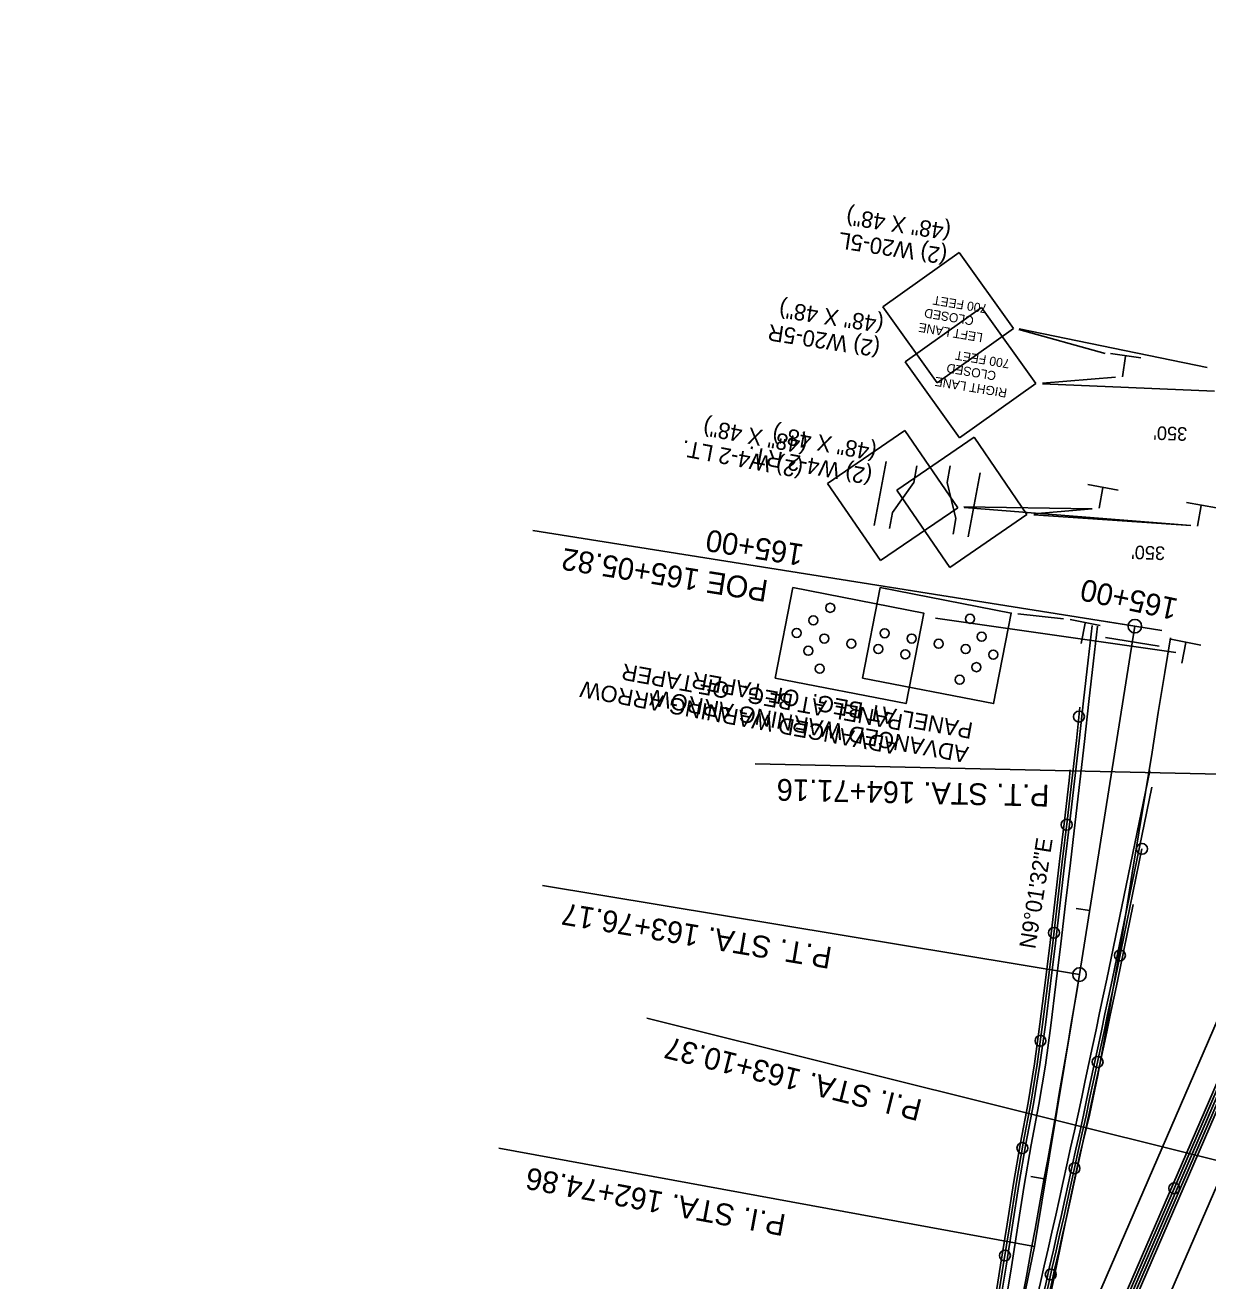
# Model space of a CAD drawing. Extents: x 659657 to 668193, y 633084 to 648639.
# Drawn here: x 661111.9 to 661546.4, y 641402.5 to 641864.1 of the extents above; entities that cross this region are included whole.
import ezdxf

# ---------------------------------------------------------------- set-up
doc = ezdxf.new("R2010")
doc.units = 0
for name, color, linetype in [('R_Border Prem', 7, 'Continuous'), ('R_Draft', 7, 'Continuous'), ('R_MOT_Stage 1_Striping', 7, 'Continuous'), ('R_MOT_Stage 1C_Striping', 7, 'Continuous'), ('R_MOT_Stage 2', 7, 'Continuous'), ('R_MOT_Stage 2_Striping', 7, 'Continuous'), ('R_MOT_Stage 3', 7, 'Continuous'), ('R_MOT_Stage 3_Striping', 7, 'Continuous'), ('R_MOT_Stage 4', 7, 'Continuous'), ('R_MOT_Stage 4_Striping', 7, 'Continuous'), ('R_MOT_Stage 4_Striping_PPM', 7, 'Continuous'), ('R_MOT_Stage 5_Striping_PPM', 7, 'Continuous'), ('S_EXISTING_ALIGNMENT', 7, 'Continuous'), ('T_Notes', 7, 'Continuous'), ('T_SIGNAL CONTROL CABINET', 7, 'Continuous')]:
    doc.layers.add(name, color=color, linetype=linetype)

msp = doc.modelspace()

# ---------------------------------------------------------------- linework, layer by layer
at = {"layer": 'R_Border Prem'}
msp.add_arc((665219.85, 639999.01), 3863.72, 156.12343, 201.98495, dxfattribs=at)
at = {"layer": 'R_Draft'}
for p, q in [((661435.19, 641740.31), (661463.19, 641760.29)), ((661463.19, 641760.29), (661483.17, 641732.29)), ((661435.19, 641740.31), (661455.17, 641712.33)), ((661510.59, 641743.37), (661521.72, 641741.76)), ((661516.1, 641742.41), (661515.01, 641734.81)), ((661512.51, 641734.61), (661485.66, 641732.49)), ((661455.17, 641712.33), (661483.17, 641732.29)), ((661548.84, 641729.52), (661485.67, 641732.19)), ((661460.5, 641712.56), (661432.13, 641693.12)), ((661479.94, 641684.18), (661460.5, 641712.56)), ((661451.7, 641702.05), (661450.56, 641695.96)), ((661462.75, 641699.46), (661458.36, 641675.94)), ((661451.57, 641664.75), (661432.13, 641693.12)), ((661450.56, 641695.96), (661453.86, 641682.77)), ((661502.35, 641695.26), (661513.41, 641693.19)), ((661507.83, 641694.07), (661506.42, 641686.52)), ((661538.51, 641688.64), (661549.58, 641686.63)), ((661479.94, 641684.18), (661451.57, 641664.75)), ((661503.93, 641686.3), (661482.41, 641684.4)), ((661540.13, 641680.09), (661482.42, 641684.01)), ((661543.99, 641687.48), (661542.62, 641679.92)), ((661453.86, 641682.77), (661452.78, 641676.98)), ((661493.35, 641645.81), (661476.62, 641647.68)), ((661495.84, 641645.54), (661506.88, 641643.38)), ((661501.3, 641644.3), (661499.83, 641636.77))]:
    msp.add_line(p, q, dxfattribs=at)
msp.add_lwpolyline([(661419.56, 641624.08), (661467.64, 641614.69), (661474.14, 641647.96), (661426.05, 641657.35)], close=True, dxfattribs=at)
for centre in [(661459.02, 641645.85), (661427.65, 641640.55), (661437.57, 641638.61), (661447.49, 641636.68), (661463.28, 641639.27), (661457.41, 641634.74), (661467.54, 641632.68), (661461.37, 641628.08), (661455.21, 641623.47)]:
    msp.add_circle(centre, 1.66, dxfattribs=at)
at = {"layer": 'R_MOT_Stage 1_Striping'}
for points in [[(661655.56, 641586.4), (661380.13, 641592.5)], [(661621.93, 641428.73), (661340.26, 641499.07)]]:
    msp.add_lwpolyline(points, dxfattribs=at)
at = {"layer": 'R_MOT_Stage 1C_Striping'}
for radius in [3799.97, 3788.97]:
    msp.add_arc((665219.85, 639999.01), radius, 157.70222, 174.95222, dxfattribs=at)
at = {"layer": 'R_MOT_Stage 2'}
for points in [[(661469.87, 641393.19), (661472.24, 641407.94), (661474.6, 641423), (661476.98, 641437.91), (661479.55, 641452.92), (661482.35, 641467.62), (661484.72, 641482.04), (661486.69, 641496.6), (661488.56, 641511.83), (661490.43, 641526.67), (661492.15, 641541.5), (661493.88, 641556.43), (661495.67, 641571.33), (661497.39, 641586.18), (661499.08, 641601.03), (661500.66, 641615.73), (661502.43, 641630.69), (661503.91, 641643.44)], [(661452.51, 641298.04), (661453.61, 641304.72), (661455.98, 641319.49), (661458.36, 641334.3), (661460.77, 641349.1), (661463.14, 641363.86), (661465.47, 641378.69), (661467.9, 641393.51), (661470.27, 641408.25), (661472.62, 641423.31), (661475.01, 641438.24), (661477.58, 641453.27), (661480.38, 641467.97), (661482.74, 641482.33), (661484.71, 641496.85), (661486.58, 641512.08), (661488.44, 641526.91), (661490.16, 641541.73), (661491.89, 641556.67), (661493.69, 641571.56), (661495.4, 641586.41), (661495.85, 641590.4)]]:
    msp.add_lwpolyline(points, dxfattribs=at)
for centre in [(661499.03, 641609.91), (661494.52, 641570.17), (661489.86, 641530.44), (661484.89, 641490.75), (661478.26, 641451.31), (661471.84, 641411.83)]:
    msp.add_circle(centre, 2, dxfattribs=at)
at = {"layer": 'R_MOT_Stage 2_Striping'}
for p, q in [((661499.23, 641515.1), (661519.57, 641643.15)), ((661482.65, 641415.14), (661499.23, 641515.1)), ((661462.54, 641315.82), (661482.65, 641415.14))]:
    msp.add_line(p, q, dxfattribs=at)
for points in [[(661519.57, 641643.15), (661298.44, 641678.27)], [(661471.85, 641392.87), (661474.22, 641407.63), (661476.57, 641422.69), (661478.96, 641437.59), (661481.52, 641452.56), (661484.32, 641467.28), (661486.7, 641481.74), (661488.67, 641496.34), (661490.55, 641511.58), (661492.41, 641526.43), (661494.14, 641541.27), (661495.87, 641556.2), (661497.66, 641571.09), (661499.37, 641585.95), (661501.07, 641600.81), (661502.65, 641615.51), (661504.42, 641630.46), (661505.89, 641643.12)], [(661509.69, 641644.72), (661529.44, 641641.58)], [(661487.01, 641389.87), (661490.06, 641404.53), (661493.11, 641419.47), (661496.16, 641434.17), (661499.38, 641448.85), (661502.86, 641463.46), (661505.96, 641478.08), (661508.65, 641492.8), (661511.23, 641507.99), (661513.78, 641522.77), (661516.2, 641537.57), (661518.61, 641552.38), (661521.08, 641567.18), (661523.49, 641581.98), (661525.87, 641596.78), (661528.12, 641611.37), (661530.57, 641626.18), (661532.63, 641638.82)], [(661508.78, 641638.97), (661528.53, 641635.83)], [(661655.56, 641586.4), (661380.13, 641592.5)], [(661499.23, 641515.1), (661301.92, 641547.83)], [(661498.03, 641539.42), (661502.97, 641538.64)], [(661621.93, 641428.73), (661340.26, 641499.07)], [(661482.65, 641415.14), (661285.95, 641451.34)], [(661481.35, 641440.93), (661486.27, 641440.04)]]:
    msp.add_lwpolyline(points, dxfattribs=at)
for centre in [(661519.57, 641643.15), (661499.23, 641515.1)]:
    msp.add_circle(centre, 2.5, dxfattribs=at)
msp.add_arc((655846.87, 642452.58), 5729.58, 348.556437, 350.582878, dxfattribs=at)
at = {"layer": 'R_MOT_Stage 3'}
msp.add_line((661511.19, 641513.05), (661525.86, 641583.97), dxfattribs=at)
for centre in [(661522.19, 641561.29), (661514.09, 641522.12), (661505.88, 641482.97), (661497.4, 641443.88), (661488.65, 641404.85)]:
    msp.add_circle(centre, 2, dxfattribs=at)
msp.add_arc((655888.72, 642681.33), 5742.57, 346.235209, 348.26165, dxfattribs=at)
at = {"layer": 'R_MOT_Stage 3_Striping'}
for p, q in [((661499.23, 641515.1), (661519.57, 641643.15)), ((661509.23, 641513.45), (661525.06, 641589.94))]:
    msp.add_line(p, q, dxfattribs=at)
for points in [[(661519.57, 641643.15), (661298.44, 641678.27)], [(661509.69, 641644.72), (661529.44, 641641.58)], [(661508.78, 641638.97), (661528.53, 641635.83)], [(661499.23, 641515.1), (661301.92, 641547.83)], [(661498.03, 641539.42), (661502.97, 641538.64)], [(661482.65, 641415.14), (661285.95, 641451.34)], [(661481.35, 641440.93), (661486.27, 641440.04)]]:
    msp.add_lwpolyline(points, dxfattribs=at)
for centre in [(661519.57, 641643.15), (661499.23, 641515.1)]:
    msp.add_circle(centre, 2.5, dxfattribs=at)
for centre, radius, start, end in [((655846.87, 642452.58), 5729.58, 348.556437, 350.582878), ((655888.72, 642681.33), 5740.57, 346.235209, 348.26165)]:
    msp.add_arc(centre, radius, start, end, dxfattribs=at)
at = {"layer": 'R_MOT_Stage 4'}
for p, q in [((661511.22, 641386.36), (661590.87, 641570.47)), ((661513.07, 641385.6), (661592.7, 641569.68))]:
    msp.add_line(p, q, dxfattribs=at)
msp.add_circle((661534.02, 641436.54), 2, dxfattribs=at)
at = {"layer": 'R_MOT_Stage 4_Striping'}
for p, q in [((661525.1, 641380.68), (661637.39, 641640.23)), ((661514.92, 641384.84), (661594.54, 641568.88))]:
    msp.add_line(p, q, dxfattribs=at)
at = {"layer": 'R_MOT_Stage 4_Striping_PPM'}
msp.add_arc((660777.38, 642087.58), 954.93, 348.72774, 348.72774, dxfattribs=at)
at = {"layer": 'R_MOT_Stage 5_Striping_PPM'}
for p, q in [((661483.39, 641314.46), (661653.82, 641708.42)), ((661654.52, 641679.82), (661494.4, 641309.7)), ((661616.74, 641652.95), (661472.37, 641319.23))]:
    msp.add_line(p, q, dxfattribs=at)
msp.add_arc((660777.38, 642087.58), 954.93, 348.72774, 348.72774, dxfattribs=at)
at = {"layer": 'S_EXISTING_ALIGNMENT'}
msp.add_line((661499.23, 641515.1), (661519.57, 641643.15), dxfattribs=at)
msp.add_arc((655846.87, 642452.58), 5729.58, 348.556437, 350.582878, dxfattribs=at)
at = {"layer": 'T_Notes'}
for p, q in [((661426.99, 641760.55), (661454.99, 641780.53)), ((661454.99, 641780.53), (661474.96, 641752.53)), ((661426.99, 641760.55), (661446.97, 641732.57)), ((661446.97, 641732.57), (661474.96, 641752.53)), ((661508.66, 641743.39), (661476.95, 641752.15)), ((661546.09, 641738.24), (661477.12, 641752.43)), ((661510.59, 641743.37), (661521.72, 641741.76)), ((661516.1, 641742.41), (661515.01, 641734.81)), ((661435.07, 641715.04), (661406.69, 641695.6)), ((661454.51, 641686.66), (661435.07, 641715.04)), ((661428.24, 641703.63), (661423.84, 641680.12)), ((661439.48, 641702.06), (661438.34, 641695.97)), ((661426.13, 641667.23), (661406.69, 641695.6)), ((661438.34, 641695.97), (661430.5, 641684.87)), ((661502.35, 641695.26), (661513.41, 641693.19)), ((661507.83, 641694.07), (661506.42, 641686.52)), ((661538.51, 641688.64), (661549.58, 641686.63)), ((661454.51, 641686.66), (661426.13, 641667.23)), ((661430.5, 641684.87), (661429.42, 641679.08)), ((661503.93, 641686.3), (661456.77, 641687.07)), ((661540.13, 641680.09), (661456.91, 641686.72)), ((661543.99, 641687.48), (661542.62, 641679.92)), ((661534.57, 641633.49), (661446.33, 641646.11)), ((661532.78, 641638.32), (661543.82, 641636.17)), ((661538.24, 641637.09), (661536.77, 641629.55))]:
    msp.add_line(p, q, dxfattribs=at)
msp.add_lwpolyline([(661387.42, 641624.08), (661435.51, 641614.69), (661442.01, 641647.96), (661393.92, 641657.35)], close=True, dxfattribs=at)
for centre in [(661407.64, 641649.89), (661401.47, 641645.28), (661395.31, 641640.67), (661405.44, 641638.61), (661415.36, 641636.68), (661399.57, 641634.09), (661425.28, 641634.74), (661435.2, 641632.8), (661403.82, 641627.51)]:
    msp.add_circle(centre, 1.66, dxfattribs=at)
at = {"layer": 'T_SIGNAL CONTROL CABINET'}
for p, q in [((661629.67, 641657.65), (661512.14, 641385.98)), ((661522.19, 641561.29), (661512.17, 641512.84)), ((661513.15, 641512.64), (661519, 641540.89))]:
    msp.add_line(p, q, dxfattribs=at)
msp.add_lwpolyline([(661453.49, 641297.86), (661454.6, 641304.56), (661456.97, 641319.33), (661459.35, 641334.14), (661461.75, 641348.94), (661464.13, 641363.71), (661466.46, 641378.53), (661468.88, 641393.35), (661471.25, 641408.1), (661473.61, 641423.15), (661476, 641438.08), (661478.57, 641453.1), (661481.36, 641467.8), (661483.73, 641482.18), (661485.7, 641496.72), (661487.57, 641511.95), (661489.43, 641526.79), (661491.16, 641541.62), (661492.89, 641556.55), (661494.68, 641571.44), (661496.39, 641586.3), (661498.08, 641601.14), (661499.4, 641613.35)], dxfattribs=at)
for radius in [5743.57, 5744.57]:
    msp.add_arc((655888.72, 642681.33), radius, 346.235209, 348.26165, dxfattribs=at)

# ---------------------------------------------------------------- texts
at = {"layer": 'R_Draft'}
for s, height, rotation, p in [('(48" X 48")', 6, 171.3021, (661427.6, 641756.79)), ('(2) W20-5R', 6, 171.3021, (661426.24, 641747.89)), ('700 FEET', 3.339, 170.506, (661473.78, 641741.12)), ('CLOSED', 3.339, 170.5068, (661468.82, 641736.7)), ('RIGHT LANE', 3.339, 170.5069, (661472.81, 641730.4)), ('(48" X 48")', 6, 169.415, (661425.05, 641709.7)), ('(2) W4-2 RT.', 6, 169.415, (661423.4, 641700.85)), ('PANEL AT BEG.  OF TAPER', 6, 169.6398, (661460.41, 641607.56)), ('ADVANCED WARNING ARROW', 6, 169.6398, (661458.8, 641598.7))]:
    msp.add_text(s, height=height, rotation=rotation, dxfattribs=at).set_placement(p)
at = {"layer": 'R_MOT_Stage 1_Striping'}
for s, rotation, p in [('165+00', 167.9602, (661535.84, 641653.12)), ('P.T. STA. 164+71.16', 178.7307, (661488.26, 641584.81)), ('P.I. STA. 163+10.37', 165.9787, (661441.87, 641468.92))]:
    msp.add_text(s, height=8, rotation=rotation, dxfattribs=at).set_placement(p)
at = {"layer": 'R_MOT_Stage 2_Striping'}
for s, height, rotation, p in [('165+00', 8, 170.9744, (661398.27, 641673.11)), ('POE 165+05.82', 8, 170.9744, (661385.22, 641659.92)), ('165+00', 8, 167.9602, (661535.84, 641653.12)), ('P.T. STA. 164+71.16', 8, 178.7307, (661488.26, 641584.81)), ('N9%%d01\'32"E', 6, 80.9744, (661482.97, 641524.28)), ('P.T. STA. 163+76.17', 8, 170.5829, (661408.7, 641525.05)), ('P.I. STA. 163+10.37', 8, 165.9787, (661441.87, 641468.92)), ('P.I. STA. 162+74.86', 8, 169.5697, (661391.75, 641426.78))]:
    msp.add_text(s, height=height, rotation=rotation, dxfattribs=at).set_placement(p)
at = {"layer": 'R_MOT_Stage 3_Striping'}
for s, height, rotation, p in [('165+00', 8, 170.9744, (661398.27, 641673.11)), ('POE 165+05.82', 8, 170.9744, (661385.22, 641659.92)), ('N9%%d01\'32"E', 6, 80.9744, (661482.97, 641524.28)), ('P.T. STA. 163+76.17', 8, 170.5829, (661408.7, 641525.05)), ('P.I. STA. 162+74.86', 8, 169.5697, (661391.75, 641426.78))]:
    msp.add_text(s, height=height, rotation=rotation, dxfattribs=at).set_placement(p)
at = {"layer": 'T_Notes'}
for s, height, rotation, p in [('(48" X 48")', 6, 171.3021, (661452.28, 641790.85)), ('(2) W20-5L', 6, 171.3021, (661450.92, 641781.95)), ('700 FEET', 3.339, 170.506, (661465.58, 641761.36)), ('CLOSED', 3.339, 170.5068, (661460.62, 641756.94)), ('LEFT LANE', 3.339, 170.5069, (661463.9, 641750.76)), ('(48" X 48")', 6, 169.415, (661399.62, 641712.18)), ('(2) W4-2 LT.', 6, 169.415, (661397.97, 641703.33)), ('PANEL AT BEG.  OF TAPER', 6, 169.6398, (661434.7, 641610.63)), ('ADVANCED WARNING ARROW', 6, 169.6398, (661433.08, 641601.78))]:
    msp.add_text(s, height=height, rotation=rotation, dxfattribs=at).set_placement(p)
at = {"layer": 'T_SIGNAL CONTROL CABINET'}
for p in [(661538.9, 641716.23), (661530.77, 641672.4)]:
    msp.add_text("350'", height=5, rotation=177.8933, dxfattribs=at).set_placement(p)

doc.saveas('drawing.dxf')
